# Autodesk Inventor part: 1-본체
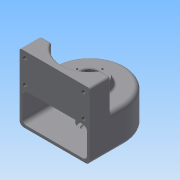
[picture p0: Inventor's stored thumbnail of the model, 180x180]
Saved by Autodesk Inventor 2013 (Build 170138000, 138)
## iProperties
Created: 2011-02
Part Number: 1-본체
Material: 일반
Document SubType Name: Modeling
Designer: Administrator
Density: 1 g/cm^3
Author: Administrator
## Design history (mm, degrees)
sketch "스케치1"
  geometry: L1 (-50, 0)-(-50, -50); L2 (-50, -50)-(50, -50); L3 (50, -50)-(50, 0); A1 r 50 centre (0, 0) between (50, 0) and (-50, 0); 1 further point
  constraints: 6 end point, 2 point on circle, 2 tangent, 1 centre point, 1 coincident, 1 parallel, 1 perpendicular, 1 vertical
  dimensions: "d0" = 50 radius of A1; "d2" = 50 distance from line of L2 point (0, 0)
extrude "돌출1" new body sketch "스케치1" distance "d3" = 50; taper "d4" = 0 deg
feature "쉘1" dims "d5" = 4
sketch "스케치2"
  geometry: C1 r 25 at (0, 0); A1 r 50 centre (0, 0) between (50, 0) and (-50, 0) reference
  constraints: 1 centre point, 1 coincident
  dimensions: "d6" = 50 diameter of C1
extrude "돌출2" join sketch "스케치2" distance "d8" = 10; taper "d9" = -20 deg
hole "구멍1" diameter "d16" = 20; stored, may be unused: countersink angle "d20" = 90 deg, drill point angle "d22" = 118 deg; dims "d14" = 10, "d15" = 10, "d17" = 6, "d18" = 28, "d19" = 10, "d21" = 8
sketch "스케치4"
  geometry: L1 (-50, 0)-(-50, -50) reference; L2 (-50, -50)-(50, -50) reference; L3 (50, -50)-(50, 0) reference; L4 (50, -20)-(34.641, -20); L5 (-34.641, -20)-(-50, -20); A1 r 50 centre (0, 0) between (50, 0) and (-50, 0) reference; A2 r 40 centre (0, 0) between (34.641, -20) and (-34.641, -20)
  constraints: 4 end point, 2 perpendicular, 2 point on circle, 2 point on line, 1 centre point, 1 coincident, 1 collinear
  dimensions: "d32" = 40 radius of A2; "d34" = 30 distance between parallel lines of L2 L4
extrude "돌출4" join sketch "스케치4" distance "d35" = 45; taper "d36" = 0 deg
sketch "스케치5"
  geometry: C1 r 14 at (0, 0) reference; C2 r 21.36 at (0, 0) reference; A1 r 18 centre (0, 0) between (0, 18) and (0, -18); 2 further points
  constraints: 4 point on circle, 2 horizontal alignment, 2 vertical alignment, 1 centre point, 1 coincident
  dimensions: "d37" = 36 diameter of A1
hole "구멍3" sketch "스케치5" at (0, 18), (0, -18), (-18, 0), (18, 0) diameter "d39" = 2.459; stored, may be unused: countersink angle "d43" = 90 deg, drill point angle "d45" = 118 deg; dims "d40" = 6, "d41" = 28, "d42" = 8, "d44" = 9
sketch "스케치6"
  geometry: L1 (100, 0)-(100, 95) reference; L2 (0, 95)-(100, 95) reference; L3 (91, 86)-(7.5, 86); L4 (7.5, 86)-(7.5, 53); L5 (7.5, 53)-(91, 53); L6 (91, 53)-(91, 86); L7 (91, 86)-(7.5, 53); L8 (7.5, 86)-(91, 53); 6 further points
  constraints: 12 end point, 4 coincident, 2 midpoint, 2 parallel, 1 horizontal, 1 perpendicular
  dimensions: "d46" = 33 distance of L5.end L3.start; "d48" = 83.5 distance of L3.start L3.end; "d49" = 9 distance between parallel lines of L2 L3; "d50" = 9 distance between parallel lines of L1 L6
hole "구멍4" sketch "스케치6" at (7.5, 86), (7.5, 53), (91, 86), (91, 53) diameter "d51" = 5.134; stored, may be unused: countersink angle "d55" = 90 deg, drill point angle "d57" = 118 deg; dims "d52" = 10, "d53" = 28, "d54" = 8, "d56" = 13
node "작업 평면1"
sketch "스케치7"
  geometry: L1 (-50, 0)-(50, 0) reference; 3 further points
  constraints: 1 midpoint, 1 vertical alignment, 1 other
  dimensions: "d58" = 25 distance from line of L1 point (0, 25)
feature "엠보싱1" sketch "스케치7" dims "d59" = 0.5, "d60" = 0
fillet "모깎기1" dims "d61" = 6
fillet "모깎기2" dims "d62" = 3
fillet "모깎기3" dims "d63" = 0.3
fillet "모깎기4" dims "d64" = 3
chamfer "모따기1" distance "d65" = 1; stored, may be unused: second distance "d66" = 2, angle "d67" = 45 deg
sketch "스케치8"
  geometry: C1 r 20 at (0, 0); A1 r 46 centre (0, 0) between (46, 0) and (-46, 0) reference
  constraints: 1 centre point, 1 coincident
  dimensions: "d68" = 40 diameter of C1
extrude "돌출5" join sketch "스케치8" distance "d70" = 13; taper "d71" = 0 deg
sketch "스케치9"
  geometry: C1 r 14 at (0, 0); A1 r 46 centre (0, 0) between (46, 0) and (-46, 0) reference
  constraints: 1 centre point, 1 coincident
  dimensions: "d72" = 28 diameter of C1
extrude "돌출6" cut sketch "스케치9" distance "d74" = 8; taper "d75" = 0 deg
sketch "스케치10"
  geometry: C1 r 14 at (0, 0) reference; C2 r 10 at (0, 0)
  constraints: 1 centre point, 1 coincident
  dimensions: "d76" = 20 diameter of C2
extrude "돌출7" cut sketch "스케치10" distance "d78" = 2; taper "d79" = 0 deg
fillet "모깎기5" dims "d80" = 3
chamfer "모따기2" distance "d81" = 1; stored, may be unused: second distance "d82" = 2, angle "d83" = 45 deg
fillet "모깎기6" dims "d84" = 6
fillet "모깎기7" dims "d85" = 3
fillet "모깎기8" dims "d86" = 0.3
node "솔리드1"
